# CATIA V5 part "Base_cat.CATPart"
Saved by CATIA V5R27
Part number: Base
Bounding box of the stored display mesh (mm): x -24 to 24, y 0 to 90, z 0 to 54
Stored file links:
  E:\_Deepak\2017_Deepak\CATIA\Resources\Tutorial Files\Tutorials\c14_catia_v5_6r2016_tut\c14tut2\c14tut2.CATParts\Base_cat_v5-6r2016.CATPart
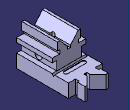
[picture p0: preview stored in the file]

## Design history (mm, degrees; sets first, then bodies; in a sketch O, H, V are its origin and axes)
Body1 (main body)
  Sketch1 on xy-plane, origin (0, 0, 0), H (1, 0, 0), V (0, 1, 0)
    line L1 (-24, 0) -> (24, 0)
    point P2 (24, 0)
    construction line L2 (-23.876, 50.8) -> (23.876, 50.8)
    point P3 (-23.876, 50.8)
    point P4 (23.876, 50.8)
    line L3 (24, 0) -> (24, 74)
    point P5 (24, 74)
    line L4 (24, 74) -> (14, 74)
    point P6 (14, 74)
    line L5 (14, 74) -> (14, 79)
    point P7 (14, 79)
    line L6 (14, 79) -> (16.5, 79)
    point P8 (16.5, 79)
    line L7 (16.5, 79) -> (16.5, 90)
    point P9 (16.5, 90)
    line L8 (16.5, 90) -> (13.5, 90)
    point P10 (13.5, 90)
    line L9 (13.5, 90) -> (2, 78.5)
    point P11 (2, 78.5)
    line L10 (2, 78.5) -> (2, 74)
    point P12 (2, 74)
    line L11 (2, 74) -> (0, 74)
    point P13 (0, 74)
    point P14 (0, 74)
    point P15 (-2, 74)
    line L12 (-2, 74) -> (0, 74)
    point P16 (-2, 78.5)
    line L13 (-2, 78.5) -> (-2, 74)
    point P17 (-13.5, 90)
    line L14 (-13.5, 90) -> (-2, 78.5)
    point P18 (-16.5, 90)
    line L15 (-16.5, 90) -> (-13.5, 90)
    point P19 (-16.5, 79)
    line L16 (-16.5, 79) -> (-16.5, 90)
    point P20 (-14, 79)
    line L17 (-14, 79) -> (-16.5, 79)
    point P21 (-14, 74)
    line L18 (-14, 74) -> (-14, 79)
    point P22 (-24, 74)
    line L19 (-24, 74) -> (-14, 74)
    point P23 (-23.876, 50.8)
    point P24 (23.876, 50.8)
    construction line L20 (23.876, 50.8) -> (-23.876, 50.8)
    point P25 (-24, 0)
    line L21 (-24, 0) -> (-24, 74)
    distance P2 V = 24
    distance L13 L10 = 4
    distance L16 L7 = 33
    distance L5 L3 = 10
    length L18 = 5
    angle L14 L9 = 90
    distance L4 L8 = 16
    distance P17 P10 = 27
    distance L1 L8 = 90
    length L1 = 48
    horizontal: L1 H, L2 H, L4 H, L6 H, L8 H, L11 H
    coincidence: H L1, P13 V, P13 P14, L12 L4
    vertical: L3 V, L5 V, L7 V, L10 V
    symmetry: P13 P14 V, P12 P15 V, L11 L12 V, P11 P16 V, L10 L13 V, P10 P17 V, L9 L14 V, P9 P18 V, L8 L15 V, P8 P19 V, L7 L16 V, P7 P20 V, L6 L17 V, P6 P21 V, L5 L18 V, P5 P22 V, L4 L19 V, P4 P23 V, P3 P24 V, L2 L20 V, P2 P25 V, L3 L21 V
  Pad1: profile Sketch1, direction (0, 0, 1), length 19
  Sketch2 on face of Pad1, origin (0, 0, 0), H (1, 0, 0), V (0, 0, 1)
    line L1 (17.5, 19) -> (17.5, 32)
    point P1 (17.5, 19)
    point P2 (17.5, 32)
    line L2 (17.5, 32) -> (24, 32)
    point P3 (24, 32)
    line L3 (24, 32) -> (24, 38)
    point P4 (24, 38)
    line L4 (24, 38) -> (13.5, 38)
    point P5 (13.5, 38)
    line L5 (13.5, 38) -> (13.5, 43)
    point P6 (13.5, 43)
    line L6 (13.5, 43) -> (16.5, 43)
    point P7 (16.5, 43)
    line L7 (16.5, 43) -> (16.5, 54)
    point P8 (16.5, 54)
    reference projected line E1 (24, 19) -> (-24, 19) from edge of Pad1
    reference projected line E2 (24, 0) -> (24, 19) from edge of Pad1
    line L8 (16.5, 54) -> (12.9083, 54)
    point P9 (12.9083, 54)
    point P10 (2, 41)
    line L9 (2, 41) -> (2, 38)
    point P11 (2, 38)
    line L10 (2, 38) -> (0, 38)
    point P12 (0, 38)
    line L11 (2, 41) -> (12.9083, 54)
    point P13 (-12.9083, 54)
    point P14 (-2, 41)
    line L12 (-2, 41) -> (-12.9083, 54)
    point P15 (0, 38)
    point P16 (-2, 38)
    line L13 (-2, 38) -> (0, 38)
    line L14 (-2, 41) -> (-2, 38)
    point P17 (-16.5, 54)
    line L15 (-16.5, 54) -> (-12.9083, 54)
    point P18 (-16.5, 43)
    line L16 (-16.5, 43) -> (-16.5, 54)
    point P19 (-13.5, 43)
    line L17 (-13.5, 43) -> (-16.5, 43)
    point P20 (-13.5, 38)
    line L18 (-13.5, 38) -> (-13.5, 43)
    point P21 (-24, 38)
    line L19 (-24, 38) -> (-13.5, 38)
    point P22 (-24, 32)
    line L20 (-24, 32) -> (-24, 38)
    point P23 (-17.5, 32)
    line L21 (-17.5, 32) -> (-24, 32)
    point P24 (-17.5, 19)
    line L22 (-17.5, 19) -> (-17.5, 32)
    line L23 (-17.5, 19) -> (17.5, 19)
    distance L2 H = 32
    distance L4 H = 38
    distance L6 H = 43
    distance L8 H = 54
    distance L9 V = 2
    length L9 = 3
    distance L22 L1 = 35
    distance L7 L16 = 33
    angle L12 L11 = 80
    distance L18 L5 = 27
    vertical: L1 V, L3 V, L5 V, L7 V, L9 V
    horizontal: L2 H, L4 H, L6 H, L8 H, L10 H, L23 H
    coincidence: P1 E1, L3 E2, P11 L4, P12 V, P12 P15
    symmetry: P9 P13 V, P10 P14 V, L11 L12 V, P12 P15 V, P11 P16 V, L10 L13 V, L9 L14 V, P8 P17 V, L8 L15 V, P7 P18 V, L7 L16 V, P6 P19 V, L6 L17 V, P5 P20 V, L5 L18 V, P4 P21 V, L4 L19 V, P3 P22 V, L3 L20 V, P2 P23 V, L2 L21 V, P1 P24 V, L1 L22 V
  Pad2: profile Sketch2, direction (0, 1, 0), length 50.8
  Sketch3 on face of Pad1, origin (4.0235, 27.8102, 0), H (1, 0, 0), V (0, -1, 0)
    point P1 (-4.0235, 2.8102)
    reference intersected line E1 through (-4.0235, 0) direction (0, 1) from yz-plane
    reference projected line E2 (-6.0235, 27.8102) -> (-16.9318, 27.8102) from edge [face of Pad2 from Sketch2.L12 | start face of Pad2]
    distance P1 E2 = 25
    coincidence: E1 P1
  Hole1: placed by Sketch3, at (0, 25, 0) direction (0, 0, 1), diameter 8, depth 54.102
  Sketch4 on face of Pad2, origin (17.5, 12.3932, 23.5222), H (0, 1, 0), V (0, 0, 1)
    point P1 (12.6068, 1.4778)
    reference projected line E1 (-12.3932, 8.4778) -> (-12.3932, -4.5222) from edge of Pad2
    reference projected line E2 (-12.3932, -23.5222) -> (61.6068, -23.5222) from edge of Pad1
    distance E1 P1 = 25
    distance E2 P1 = 25
  Hole2: placed by Sketch4, at (17.5, 25, 25) direction (-1, 0, 0), diameter 10, depth 54.102
  Sketch5 on face of Pad1, origin (0, 0, 19), H (1, 0, 0), V (0, 1, 0)
    construction line L1 (-24, 59) -> (24, 59)
    point P1 (-24, 59)
    point P2 (24, 59)
    construction line L2 (-12.5, 59) -> (12.5, 59)
    point P3 (-12.5, 59)
    point P4 (12.5, 59)
    line L3 (-12.5, 62) -> (12.5, 62)
    line L4 (12.5, 56) -> (-12.5, 56)
    arc A1 centre (12.5, 59) radius 3 from (12.5, 62) to (12.5, 56) cw
    arc A2 centre (-12.5, 59) radius 3 from (-12.5, 56) to (-12.5, 62) cw
    reference projected line E1 (24, 74) -> (24, 0) from edge of Pad1
    reference projected line E2 (-24, 74) -> (-24, 0) from edge of Pad1
    reference projected line E3 (24, 74) -> (14, 74) from edge [face of Pad1 from Sketch1.L4 | end face of Pad1]
    radius A1 = 3
    distance L2 E3 = 15
    length L2 = 25
    distance V P4 = 12.5
    horizontal: L1 H, L2 H
    coincidence: P3 L1, P2 E1, P1 E2
    tangency: A1 L3, A2 L3, A1 L4, A2 L4
    parallelism: L2 L3
  Pocket1: profile Sketch5, direction (0, 0, -1), length 1
  Sketch6 on face of Pad1, origin (24, 0, 0), H (0, 1, 0), V (0, 0, 1)
    point P1 (50.8, 19)
    line L1 (50.8, 19) -> (52.5321, 16)
    point P2 (52.5321, 16)
    line L2 (52.5321, 16) -> (54.2641, 19)
    line L3 (54.2641, 19) -> (50.8, 19)
    reference projected line E1 (74, 19) -> (0, 19) from edge of Pad1
    construction line L4 (52.5321, 16) -> (52.5321, 29.45)
    reference projected line E2 (50.8, 19) -> (50.8, 32) from edge [end face of Pad2 | face of Pad2 from Sketch2.L1]
    angle L1 L2 = 60
    distance P2 L3 = 3
    angle L4 L2 = 30
    horizontal: L3 H
    coincidence: L3 E1, P1 E2
    vertical: L4 V
  Pocket2: profile Sketch6, direction (-1, 0, 0), through (limit type 6)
